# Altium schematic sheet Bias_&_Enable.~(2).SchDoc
size 431 x 279 mm; Date: Not shown in title block; ApprovedBy: Not shown in title block; CheckedBy: Not shown in title block; Author: Not shown in title block; CompanyName: Not shown in title block; Engineer: Not shown in title block; Organization: Not shown in title block; Address1: Not shown in title block; Address2: Not shown in title block; Address3: Not shown in title block; Address4: Not shown in title block; DocumentNumber: 3; Revision: Use project parameter SCH_Rev; SheetNumber: 4; SheetTotal: 4; PageSetup: Record=PageOptions¦CenterHorizontal=True¦CenterVertical=True¦PrintScale=1.00¦XCorrection=1.00¦YCorrection=1.00¦PrintKind=0¦BorderSize=5000000¦LeftOffset=0¦BottomOffset=0¦Orientation=2¦PaperLength=1000¦PaperWidth=1000¦Scale=100¦PaperSource=15¦PrintQuality=600¦MediaType=1¦DitherType=10¦PaperKind=Letter¦PrintScaleMode=1
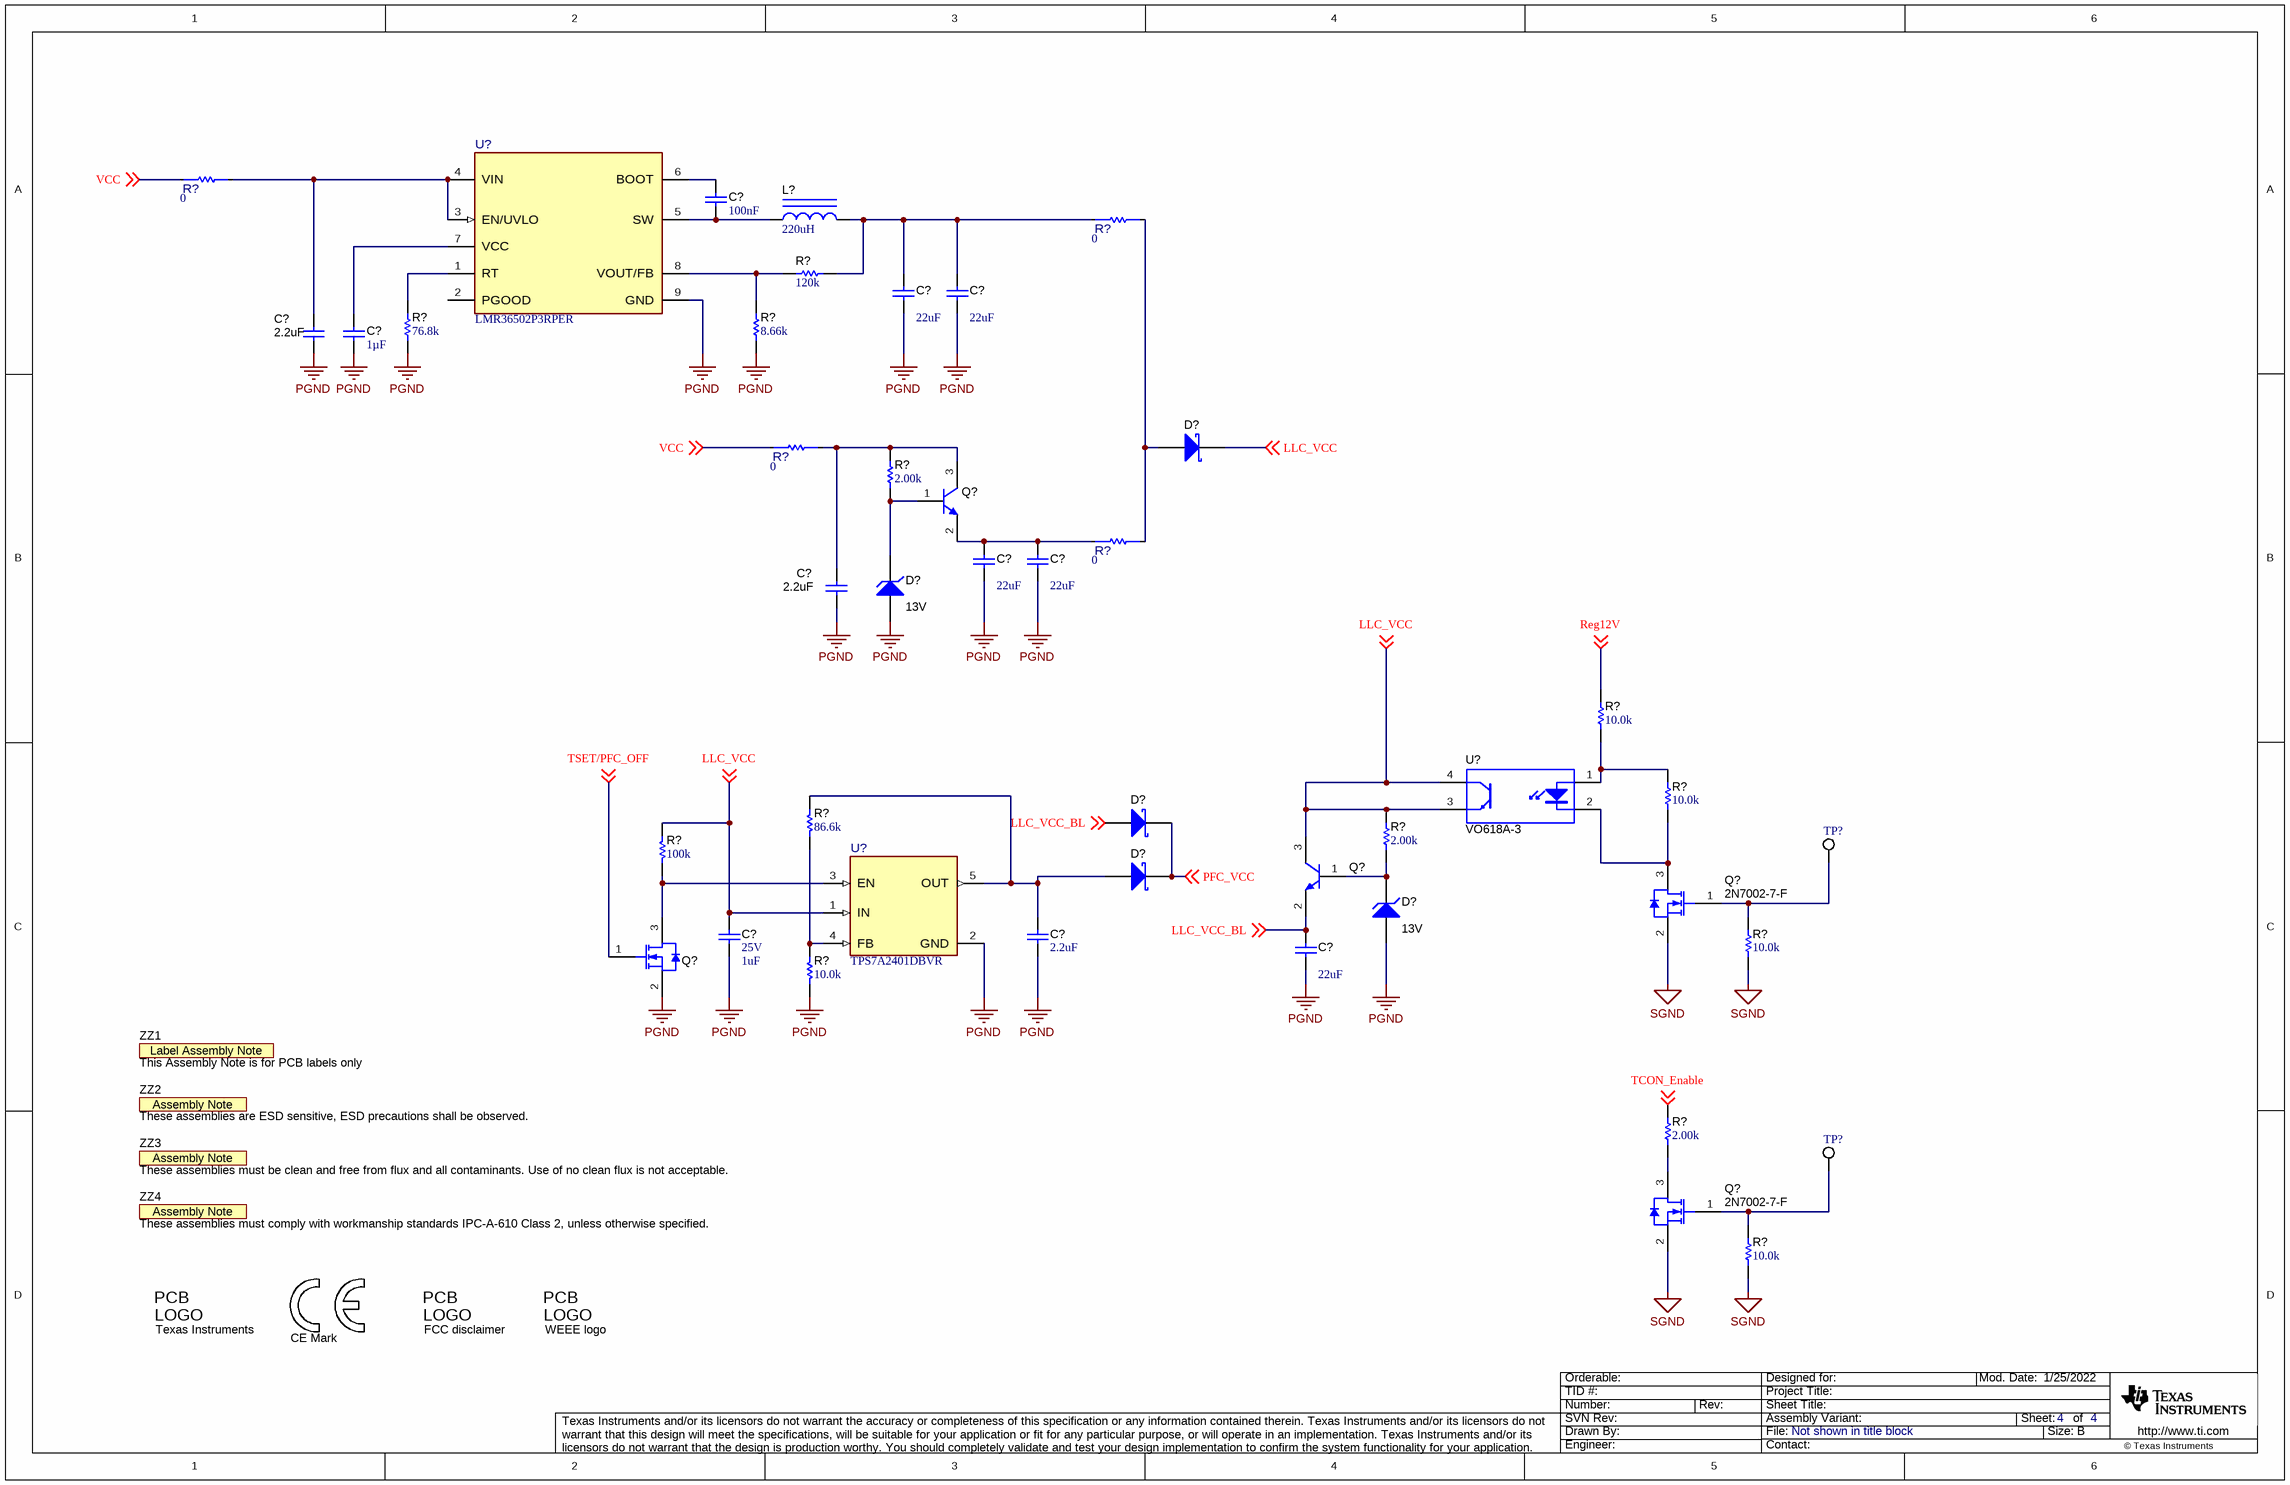
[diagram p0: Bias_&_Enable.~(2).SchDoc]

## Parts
(Parts that share a designator on the sheet are numbered #1, #2 ... from top to bottom, then left to right.)
C?#1  Cap_F: 100nF  [0603]  (hidden comment: C0603X104K3RACTU)
C?#2  ValueDisplayed: 22uF  [1210_270]  (hidden comment: GRM32ER61E226KE15L)
C?#3  ValueDisplayed: 22uF  [1210_270]  (hidden comment: GRM32ER61E226KE15L)
C?#4  ValueDisplayed: 2.2uF  [0805L]  (hidden comment: C2012X7R1V225K085AC)
C?#5  Cap_F: 1µF  [0603]  (hidden comment: C1608X7R1V105K080AC)
C?#6  ValueDisplayed: 22uF  [1210_270]  (hidden comment: GRM32ER61E226KE15L)
C?#7  ValueDisplayed: 22uF  [1210_270]  (hidden comment: GRM32ER61E226KE15L)
C?#8  ValueDisplayed: 2.2uF  [0805L]  (hidden comment: C2012X7R1V225K085AC)
C?#9  ValueDisplayed: 2.2uF  [0805_HV]  (hidden comment: Capacitor)
C?#10  VDC_V: 25V  ValueDisplayed: 1uF  [0603]  (hidden comment: C1608X5R1E105K080AC)
C?#11  ValueDisplayed: 22uF  [1210_270]  (hidden comment: GRM32ER61E226KE15L)
D?#1  BAT54WS-7-F  [SOD-323]  (value not drawn)
D?#2  value 13V  [SOD-123]  (hidden comment: MMSZ5243B-7-F)
D?#3  BAT54WS-7-F  [SOD-323]  (value not drawn)
D?#4  BAT54WS-7-F  [SOD-323]  (value not drawn)
D?#5  value 13V  [SOD-123]  (hidden comment: MMSZ5243B-7-F)
L?  ValueDisplayed: 220uH  [MSS5121]  (hidden comment: MSS5121-224MLB)
Logo1  CE Mark  [CE_Mark_5mm]  (no BOM)
Logo2  Texas Instruments  [TI_Stacked_Overlay_Small]  (no BOM)
Logo3  FCC disclaimer  [FCC_disclaimer]  (no BOM)
Logo4  WEEE logo  [WEEE_Minimum]  (no BOM)
Q?#1  MMBTA05LT1G  [SOT-23]  (value not drawn)
Q?#2  MMBTA05LT1G  [SOT-23]  (value not drawn)
Q?#3  2N7002-7-F  [SOT-23]
Q?#4  2N7002-7-F  [SOT-23]  (value not drawn)
Q?#5  2N7002-7-F  [SOT-23]
R?#1  value 0  [FP-RMCF1206ZT0R00_1206-MFG]  (hidden comment: RMCF1206ZT0R00)
R?#2  value 0  [FP-RMCF1206ZT0R00_1206-MFG]  (hidden comment: RMCF1206ZT0R00)
R?#3  ValueDisplayed: 120k  [0603]  (hidden comment: RC0603FR-07120KL)
R?#4  ValueDisplayed: 76.8k  [0603]  (hidden comment: RC0603FR-0776K8L)
R?#5  ValueDisplayed: 8.66k  [0603]  (hidden comment: RC0603FR-078K66L)
R?#6  value 0  [FP-RMCF1206ZT0R00_1206-MFG]  (hidden comment: RMCF1206ZT0R00)
R?#7  ValueDisplayed: 2.00k  [0603]  (hidden comment: RC0603FR-072KL)
R?#8  value 0  [FP-RMCF1206ZT0R00_1206-MFG]  (hidden comment: RMCF1206ZT0R00)
R?#9  ValueDisplayed: 10.0k  [0603]  (hidden comment: M55342K12B10E0T)
R?#10  ValueDisplayed: 10.0k  [0603]  (hidden comment: M55342K12B10E0T)
R?#11  ValueDisplayed: 86.6k  [0603]  (hidden comment: RC0603FR-0786K6L)
R?#12  ValueDisplayed: 2.00k  [0603]  (hidden comment: RC0603FR-072KL)
R?#13  ValueDisplayed: 100k  [0603]  (hidden comment: RC0603FR-07100KL)
R?#14  ValueDisplayed: 10.0k  [0603]  (hidden comment: M55342K12B10E0T)
R?#15  ValueDisplayed: 10.0k  [0603]  (hidden comment: M55342K12B10E0T)
R?#16  ValueDisplayed: 2.00k  [0603]  (hidden comment: RC0603FR-072KL)
R?#17  ValueDisplayed: 10.0k  [0603]  (hidden comment: M55342K12B10E0T)
TP?#1  5012  [Keystone5012]  (value not drawn)
TP?#2  5012  [Keystone5012]  (value not drawn)
U?#1  LMR36502P3RPER  [RPE0009B-MFG]
U?#2  VO618A-3  [DIP-4]
U?#3  TPS7A2401DBVR  [DBV0005A-MFG]
ZZ1  This Assembly Note is for PCB labels only  [AssemblyNoteLabel]  (no BOM)
ZZ2  These assemblies are ESD sensitive, ESD precautions shall be observed.  [AssemblyNote]  (no BOM)
ZZ3  These assemblies must be clean and free from flux and all contaminants. Use of no clean flux is not acceptable.  [AssemblyNote]  (no BOM)
ZZ4  These assemblies must comply with workmanship standards IPC-A-610 Class 2, unless otherwise specified.  [AssemblyNote]  (no BOM)

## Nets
PGND: C?#2.2 C?#3.2 C?#4.2 C?#5.2 C?#6.2 C?#7.2 C?#8.2 C?#9.1 C?#10.2 C?#11.2 D?#2.2(A) D?#5.2(A) Q?#4.2(S) R?#4.1 R?#5.1 R?#15.1 U?#1.9(GND) U?#3.2(GND)
SGND: Q?#3.2(S) Q?#5.2(S) R?#14.1 R?#17.1
LLC_VCC: C?#10.1 D?#1.1(K) Q?#2.3(C) R?#12.2 R?#13.2 U?#2.3(E) U?#2.4(C) U?#3.1(IN) ; off-sheet LLC_VCC
LLC_VCC_BL: C?#11.1 D?#3.2(A) Q?#2.2(E) ; off-sheet LLC_VCC_BL
PFC_VCC: D?#3.1(K) D?#4.1(K) ; off-sheet PFC_VCC
Reg12V: R?#9.2 ; off-sheet Reg12V
TCON_Enable: R?#16.2 ; off-sheet TCON_Enable
TSET/PFC_OFF: Q?#4.1(G) ; off-sheet TSET/PFC_OFF
VCC: R?#1.1 R?#6.1 ; off-sheet VCC
NetC?#1_1: C?#1.1 U?#1.6(BOOT)
NetC?#1_2: C?#1.2 L?.1 U?#1.5(SW)
NetC?#2_1: C?#2.1 C?#3.1 L?.2 R?#2.1 R?#3.2
NetC?#4_1: C?#4.1 R?#1.2 U?#1.3(EN/UVLO) U?#1.4(VIN)
NetC?#5_1: C?#5.1 U?#1.7(VCC)
NetC?#6_1: C?#6.1 C?#7.1 Q?#1.2(E) R?#8.1
NetC?#8_1: C?#8.1 Q?#1.3(C) R?#6.2 R?#7.2
NetC?#9_2: C?#9.2 D?#4.2(A) R?#11.1 U?#3.5(OUT)
NetD?#1_2: D?#1.2(A) R?#2.2 R?#8.2
NetD?#2_1: D?#2.1(K) Q?#1.1(B) R?#7.1
NetD?#5_1: D?#5.1(K) Q?#2.1(B) R?#12.1
NetQ?#3_1: Q?#3.1(G) R?#14.2 TP?#1.1
NetQ?#3_3: Q?#3.3(D) R?#10.1 U?#2.2(K)
NetQ?#4_3: Q?#4.3(D) R?#13.1 U?#3.3(EN)
NetQ?#5_1: Q?#5.1(G) R?#17.2 TP?#2.1
NetQ?#5_3: Q?#5.3(D) R?#16.1
NetR?#3_1: R?#3.1 R?#5.2 U?#1.8(VOUT/FB)
NetR?#4_2: R?#4.2 U?#1.1(RT)
NetR?#9_1: R?#9.1 R?#10.2 U?#2.1(A)
NetR?#11_2: R?#11.2 R?#15.2 U?#3.4(FB)

Not connected (* = marked no-connect by the designer): U?#1 2(PGOOD)

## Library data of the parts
C?#1 = CMP-0006979-5: CAP, CERM, 0.1 uF, 25 V, +/- 10%, X7R, 0603; Manufacturer: Kemet; TaMin_C: -55°C; Polarized: N; SizeAreaWB_mm2: 4.68; Value1: Unknown; U/M: EA; Value: 0.1uF; TaMax_C: 125°C; SizeZ_mm: 1; SizeX_mm: 1.6; SizeY_mm: 0.8; Value2: 25V; SizeArea_mm2: 1.28; AEC Category: Q200
C?#2 C?#3 C?#6 C?#7 C?#11 = CMP-0009213-2: CAP, CERM, 22 uF, 25 V, +/- 10%, X5R, 1210; Manufacturer: MuRata; TaMin_C: -55°C; ESR_ohm: 2m; Polarized: N; SizeAreaWB_mm2: 14.7; Value1: 0.002 ohm; U/M: EA; Value: 22uF; TaMax_C: 85°C; SizeZ_mm: 2.7; SizeX_mm: 3.2; SizeY_mm: 2.5; Cap_Case: 1210; Value2: 25V; SizeArea_mm2: 8; Cap_F: 22µF; IRMS_A: 3.67A; AEC Category: Q200
C?#4 C?#8 = CMP-0007883-2: CAP, CERM, 2.2 uF, 35 V, +/- 10%, X7R, 0805; Manufacturer: TDK; TaMin_C: -55°C; Polarized: N; SizeAreaWB_mm2: 6.75; Value1: Unknown; U/M: EA; Value: 2.2uF; TaMax_C: 125°C; SizeZ_mm: 1.45; SizeX_mm: 2; SizeY_mm: 1.25; Cap_Case: 0805; Value2: 35V; SizeArea_mm2: 2.5; CompType: Capacitor; Cap_F: 2.2µF; AEC Category: Q200
C?#5 = CMP-0007052-4: CAP, CERM, 1 uF, 35 V, +/- 10%, X7R, 0603; Manufacturer: TDK; TaMin_C: -55°C; Polarized: N; SizeAreaWB_mm2: 4.68; Value1: Unknown; U/M: EA; Value: 1uF; TaMax_C: 125°C; SizeZ_mm: 1; SizeX_mm: 1.6; SizeY_mm: 0.8; Value2: 35V; SizeArea_mm2: 1.28; AEC Category: Q200
C?#9 = CMP-0007877-2: CAP, CERM, 2.2 uF, 50 V, +/- 10%, X7R, 0805; PartNumber: C2012X7R1H225K125AC; Manufacturer: TDK; Polarized: N; Value: 2.2uF; U/M: EA; Cap_F: 2.2µF; ESR_ohm: 3.66m; Value1: 0.00366 ohm; VDC_V: 50V; IRMS_A: 3.41207A; TaMin_C: -55°C; TaMax_C: 125°C; Cap_Case: 0805; SizeArea_mm2: 2.5; SizeAreaWB_mm2: 6.75; SizeX_mm: 2; SizeY_mm: 1.25; SizeZ_mm: 1.45; AEC Category: Q200
C?#10 = CMP-0007006-5: CAP, CERM, 1 uF, 25 V, +/- 10%, X5R, 0603; Manufacturer: TDK; TaMin_C: -55°C; Polarized: N; SizeAreaWB_mm2: 4.68; Value1: Unknown; U/M: EA; Value: 1uF; TaMax_C: 85°C; SizeZ_mm: 1; SizeX_mm: 1.6; SizeY_mm: 0.8; SizeArea_mm2: 1.28; Cap_F: 1µF; AEC Category: Q200
D?#1 D?#3 D?#4 = CMP-0028458-2: Diode, Schottky, 30 V, 0.2 A, SOD-323; Manufacturer: Diodes Inc.; SizeArea_mm2: 3.645; Green_Lifecycle: Active; Io_A: 200mA; TJmax_C: 125°C; Value2: 0.7V; Vf_V: 700mV; Green_REACh: Passed; Value1: 0.2A; Vr_V: 30V; AEC Category: Q101; SizeAreaWB_mm2: 8.695; SizeY_mm: 1.35; Value: 30V; SizeX_mm: 2.7; SizeZ_mm: 1
D?#2 D?#5 = CMP-0005752-4: Diode, Zener, 13 V, 500 mW, SOD-123; Manufacturer: Diodes Inc.; Value1: 0.5W; SizeAreaWB_mm2: 13.095; RJA_CperW: 350; AEC Category: Q101; SizeZ_mm: 1.35; SizeX_mm: 3.85; Power_W: 500mW; SizeArea_mm2: 6.545; SizeY_mm: 1.7
L? = CMP-0061952-2: Inductor, Shielded Drum Core, Ferrite, 220 uH, 0.25 A, 3.1 ohm, SMD; Manufacturer: Coilcraft; Isat: 0.25A @ 30% inductance drop; Irms: 0.29A @ 40C rise; Green_Lifecycle: Not Set; SizeAreaWB_mm2: 54.76; DCR_ohm: 3.1; Green_REACh: Incomplete; Value1: 3.1 ohm; Value: 220uH; Imax_A: 2.5dA; SizeZ_mm: 2.2; SizeX_mm: 5.4; Value2: 0.25A; SizeArea_mm2: 29.16; Ind_H: 220µH; AEC Category: Q200
Logo1 = CMP-0074844-1: SymbolCreator: a0412235
Logo2 = CMP-0074838-1: Texas Instrument Corporate Signature; SymbolCreator: a0412235; Lib Reference: TI_Logo; Library Reference: Logo
Logo3 = CMP-0074847-1: FCC_disclaimer; Library Reference: Logo
Logo4 = CMP-0074769-1
Q?#1 Q?#2 = CMP-0000488-2: Transistor, NPN, 60 V, 0.5 A, AEC-Q101, SOT-23; Manufacturer: ON Semiconductor; TaMax_C: 150°C; Value1: 0.5 A; Vcesat1_V: 2.5dV; SizeX_mm: 2.5; SizeY_mm: 3; TaMin_C: -55°C; IcRated_A: 5dA; CompType: BJT; SizeZ_mm: 1.1; AEC Qualified: Y; Value: 60 V; SizeArea_mm2: 7.5; NPN: 1; Vceo_V: 60V; PNP: 0; AEC Category: Q101; SizeAreaWB_mm2: 14; U/M: EA
Q?#3-Q?#5 = CMP-0000769-1: MOSFET, N-CH, 60 V, 0.17 A, SOT-23; Alternate Manufacturer: None; Manufacturer: Diodes Inc.; SizeZ_mm: 1.1; ChType: N; Value2: 223 nC; Value1: 7; VdsMax_V: 60V; SizeX_mm: 2.5; SizeY_mm: 3; Vgs_V: 20V; Value: 60V; Rdson45_ohm: 7.5; AEC Category: Q101; IdsMax_A: 1.7dA; SizeAreaWB_mm2: 14; U/M: EA; QgTyp_nC: 223
R?#1 R?#2 R?#6 R?#8 = CMP-0093609-1: 0Ω ±0 0.25W 1206 Thick Film Chip Resistor AEC-Q200 compliant; Manufacturer: Stackpole Electronics; AEC Qualified: Yes; VDC_V: 200V; AEC Grade: Grade 0; Power_W: 250mW; SizeZ_mm: 0.7mm
R?#3 = CMP-0022768-4: RES, 120 k, 1%, 0.1 W, 0603; Manufacturer: Yageo; Power_W: 100mW; TempCo: 100 ppm/C; Value: 120k; SizeX_mm: 1.6; SizeY_mm: 0.8; SizeZ_mm: 1; Value2: 0.1W; SizeArea_mm2: 1.28; AEC Qualified: N; VDC_V: 75V; AEC Category: Q200; SizeAreaWB_mm2: 4.68
R?#4 = CMP-0023271-5: RES, 76.8 k, 1%, 0.1 W, 0603; Manufacturer: Yageo; Power_W: 100mW; TempCo: 100 ppm/C; Value_Code: 76k8; Value: 76.8k; EIA_Code: E96; SizeX_mm: 1.6; SizeY_mm: 0.8; SizeZ_mm: 1; Value2: 0.1W; SizeArea_mm2: 1.28; AEC Qualified: N; VDC_V: 75V; AEC Category: Q200; SizeAreaWB_mm2: 4.68
R?#5 = CMP-0023310-5: RES, 8.66 k, 1%, 0.1 W, 0603; Manufacturer: Yageo; Power_W: 100mW; TempCo: 100 ppm/C; Value_Code: 8k66; Value: 8.66k; EIA_Code: E96; SizeX_mm: 1.6; SizeY_mm: 0.8; SizeZ_mm: 1; Value2: 0.1W; SizeArea_mm2: 1.28; AEC Qualified: N; VDC_V: 75V; AEC Category: Q200; SizeAreaWB_mm2: 4.68
R?#7 R?#12 R?#16 = CMP-0023000-5: RES, 2.00 k, 1%, 0.1 W, 0603; Manufacturer: Yageo; Power_W: 100mW; TempCo: 100 ppm/C; Value_Code: 2k00; Value: 2.00k; EIA_Code: E96; Res_ohm: 2k; SizeX_mm: 1.6; SizeY_mm: 0.8; SizeZ_mm: 1; Value2: 0.1W; SizeArea_mm2: 1.28; AEC Qualified: N; VDC_V: 75V; AEC Category: Q200; SizeAreaWB_mm2: 4.68
R?#9 R?#10 R?#14 R?#15 R?#17 = CMP-0080488-1: RES, 10.0 k, 1%, 0.1 W, 0603; Manufacturer: TT Electronics/IRC; Power_W: 100mW; TempCo: 100 ppm/C; SizeAreaWB_mm2: 4.68; Value_Code: 10k0; Value: 10.0k; EIA_Code: E96; Res_ohm: 10k; SizeX_mm: 1.6; SizeY_mm: 0.8; SizeZ_mm: 1; Value2: 0.1W; SizeArea_mm2: 1.28; AEC Qualified: N; AEC Category: Q200
R?#11 = CMP-0023301-5: RES, 86.6 k, 1%, 0.1 W, 0603; Manufacturer: Yageo; Power_W: 100mW; TempCo: 100 ppm/C; Value_Code: 86k6; Value: 86.6k; EIA_Code: E96; SizeX_mm: 1.6; SizeY_mm: 0.8; SizeZ_mm: 1; Value2: 0.1W; SizeArea_mm2: 1.28; AEC Qualified: N; VDC_V: 75V; AEC Category: Q200; SizeAreaWB_mm2: 4.68
R?#13 = CMP-0022735-5: RES, 100 k, 1%, 0.1 W, 0603; Manufacturer: Yageo; Power_W: 100mW; TempCo: 100 ppm/C; Value: 100k; EIA_Code: E96; SizeX_mm: 1.6; SizeY_mm: 0.8; SizeZ_mm: 1; Value2: 0.1W; SizeArea_mm2: 1.28; AEC Qualified: N; VDC_V: 75V; AEC Category: Q200; SizeAreaWB_mm2: 4.68
TP?#1 TP?#2 = CMP-0055149-2: Test Point, Multipurpose, White, TH; Manufacturer: Keystone Electronics; ContactFinish: Silver; CT: TRUE; CNHeader: FALSE; Green_Lifecycle: Active; Green_REACh: Passed
U?#1 = CMP-0120075-1: 3-V to 65-V, 150-mA Wide VIN Synchronous Buck Converter Optimized for Size and Light Load Efficiency; Manufacturer: Texas Instruments; SizeZ_mm: 1mm; AEC Qualified: No; Max Duty Cycle: 98%; Max Supply Voltage: 65V; Min Supply Voltage: 3.6V; Nominal Supply Current: 0.672-18uA; Number Of Outputs: 1; Output Type: Fixed,AdjustableProgrammable; Output Voltage: 3.3/1-16V; Standoff Height: 0mm; Switching Frequency: 0.2-2.2MHz; TJmax_C: +150°C
U?#2 = CMP-0083653-1: Optocoupler, 5.3 kV, 100-200% CTR, SMT; Manufacturer: Vishay-Semiconductor; CTR (Max): 200%; SizeAreaWB_mm2: 71.064; CTR (Min): 100%; SizeZ_mm: 5; SizeX_mm: 8.8; SizeY_mm: 4.58; SizeArea_mm2: 40.304; Voltage_Isolation_Vrms: 5.3kV
U?#3 = CMP-0089843-1: Linear Voltage Regulator IC 1 Output 200mA SOT-23-5; Manufacturer: Texas Instruments; Output Type: AdjustableProgrammable; Accuracy Percentage: 2%; AEC Qualified: No; Max Supply Voltage: 18V; Dropout Voltage: 160mV; SizeZ_mm: 1.45mm; Output Voltage: 1.24-17.75V; Min Supply Voltage: 2.4V; TJmax_C: +125°C; Nominal Supply Current: 2uA; Number Of Outputs: 1; Standoff Height: 0mm
ZZ1 = CMP-0003616-3
ZZ2 = CMP-0077236-1
ZZ3 = CMP-0077237-1
ZZ4 = CMP-0077238-1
